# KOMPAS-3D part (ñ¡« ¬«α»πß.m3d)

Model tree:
1. Эскиз:1
2. Операция выдавливания:1
     Расстояние 1 = 2
3. Эскиз:3
4. Операция выдавливания:2
     Расстояние 1 = 4.8
5. Эскиз:4
6. Операция выдавливания:3
     Расстояние 1 = 2.5
7. Скругление:1
     Радиус = 2
8. Скругление:2
     Радиус = 2
9. Скругление:3
     Радиус = 2
10. Скругление:5
     Радиус = 1
11. Скругление:6
     Радиус = 1
12. Эскиз:5
13. Операция выдавливания:4
     Расстояние 1 = 2.5
14. Эскиз:6
15. Операция выдавливания:5
     Расстояние 1 = 2
16. Эскиз:7
17. Операция выдавливания:6
     Расстояние 1 = 1
18. Зеркальный массив:1  (with: Операция выдавливания:1, Операция выдавливания:2, Операция выдавливания:3, Скругление:1, Скругление:2, Скругление:3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)  (labels: Экземпляр ( 1 ); Экземпляр ( 2 ))
19. Скругление:7
     Радиус = 2
20. Скругление:8
     Радиус = 1
21. Скругление:9
     Радиус = 1
22. Скругление:10
     Радиус = 1
23. Скругление:11
     Радиус = 1
24. Эскиз:11
25. Вырезать элемент выдавливания:3
     Расстояние 1 = 0.5
26. Скругление:16
     Радиус = 0.5
27. Эскиз:12
28. Операция выдавливания:8
     Расстояние 1 = 5; Угол 1 = 20
29. Эскиз:13
30. Операция выдавливания:9
     Расстояние 1 = 3; Угол 1 = 20
31. Эскиз:14
32. Вырезать элемент выдавливания:4
     Расстояние 2 = 64; Расстояние 1 = 64
33. Эскиз:15
34. Вырезать элемент выдавливания:5
     Расстояние 1 = 0.8
35. Эскиз:16
36. Вырезать элемент выдавливания:6
     Расстояние 1 = 0.5
37. Скругление:17
     Радиус = 1
38. Скругление:18
     Радиус = 1
39. Скругление:19
     Радиус = 1
40. Скругление:20
     Радиус = 1
41. Скругление:21
     Радиус = 1
42. Скругление:22
     Радиус = 2
43. Скругление:23
     Радиус = 2
44. Скругление:24
     Радиус = 1
45. Скругление:25
     Радиус = 1
46. Скругление:26
     Радиус = 1
47. Скругление:27
     Радиус = 1
48. Скругление:29
     Радиус = 1
49. Эскиз:17
50. Вырезать элемент выдавливания:7
     Расстояние 1 = 10
51. Скругление:30
     Радиус = 2
52. Эскиз:18
53. Вырезать элемент выдавливания:8
     Расстояние 1 = 6
54. Эскиз:19
55. Вырезать элемент выдавливания:9
     Расстояние 1 = 6
56. Эскиз:20
57. Операция выдавливания:10
     Расстояние 1 = 3; Угол 1 = 6
58. Скругление:31
     Радиус = 1
59. Эскиз:21
60. Вырезать элемент выдавливания:10
     Расстояние 1 = 0.7
61. Скругление:32
     Радиус = 0.5
62. Эскиз:22
63. Вырезать элемент выдавливания:11
     Расстояние 1 = 0.5
64. Скругление:33
     Радиус = 0.3

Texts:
  stalker61
  Сплав АЛ8  ГОСТ 1583-93
  Экземпляр ( 1 )
  Экземпляр ( 2 )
